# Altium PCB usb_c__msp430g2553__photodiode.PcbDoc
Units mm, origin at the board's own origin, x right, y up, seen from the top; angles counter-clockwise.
Board outline 56 x 30 mm, 2 copper layers (Top, Bottom), stack 0 mm thick; 27 components, 18 nets, 126 pads, 36 vias.
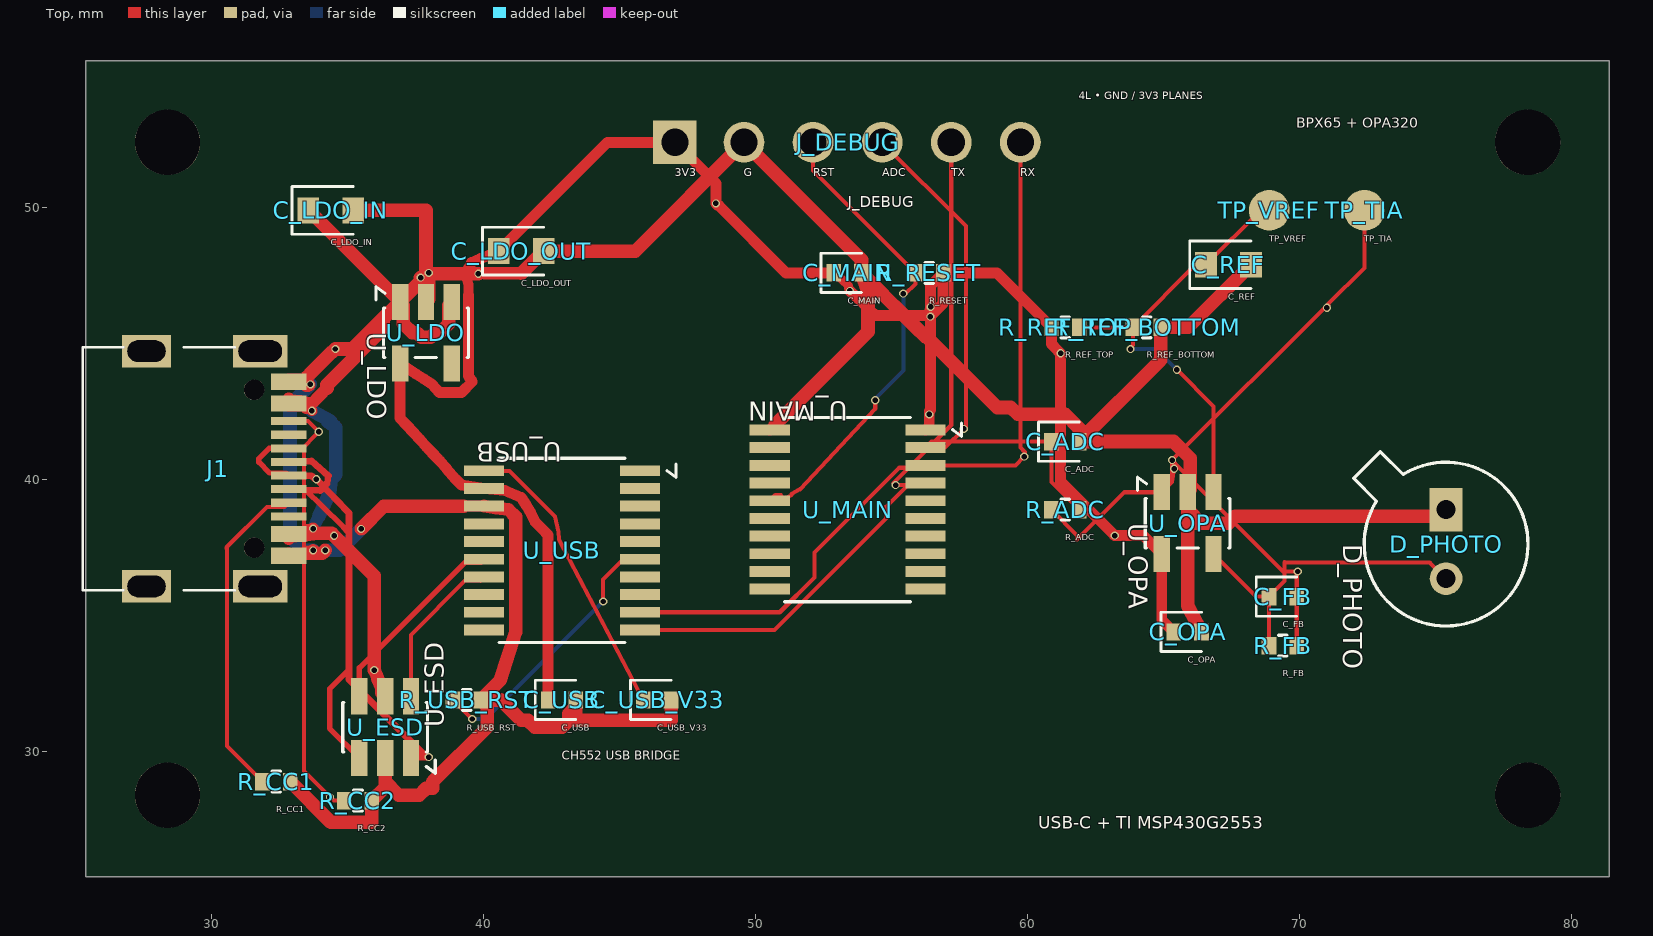
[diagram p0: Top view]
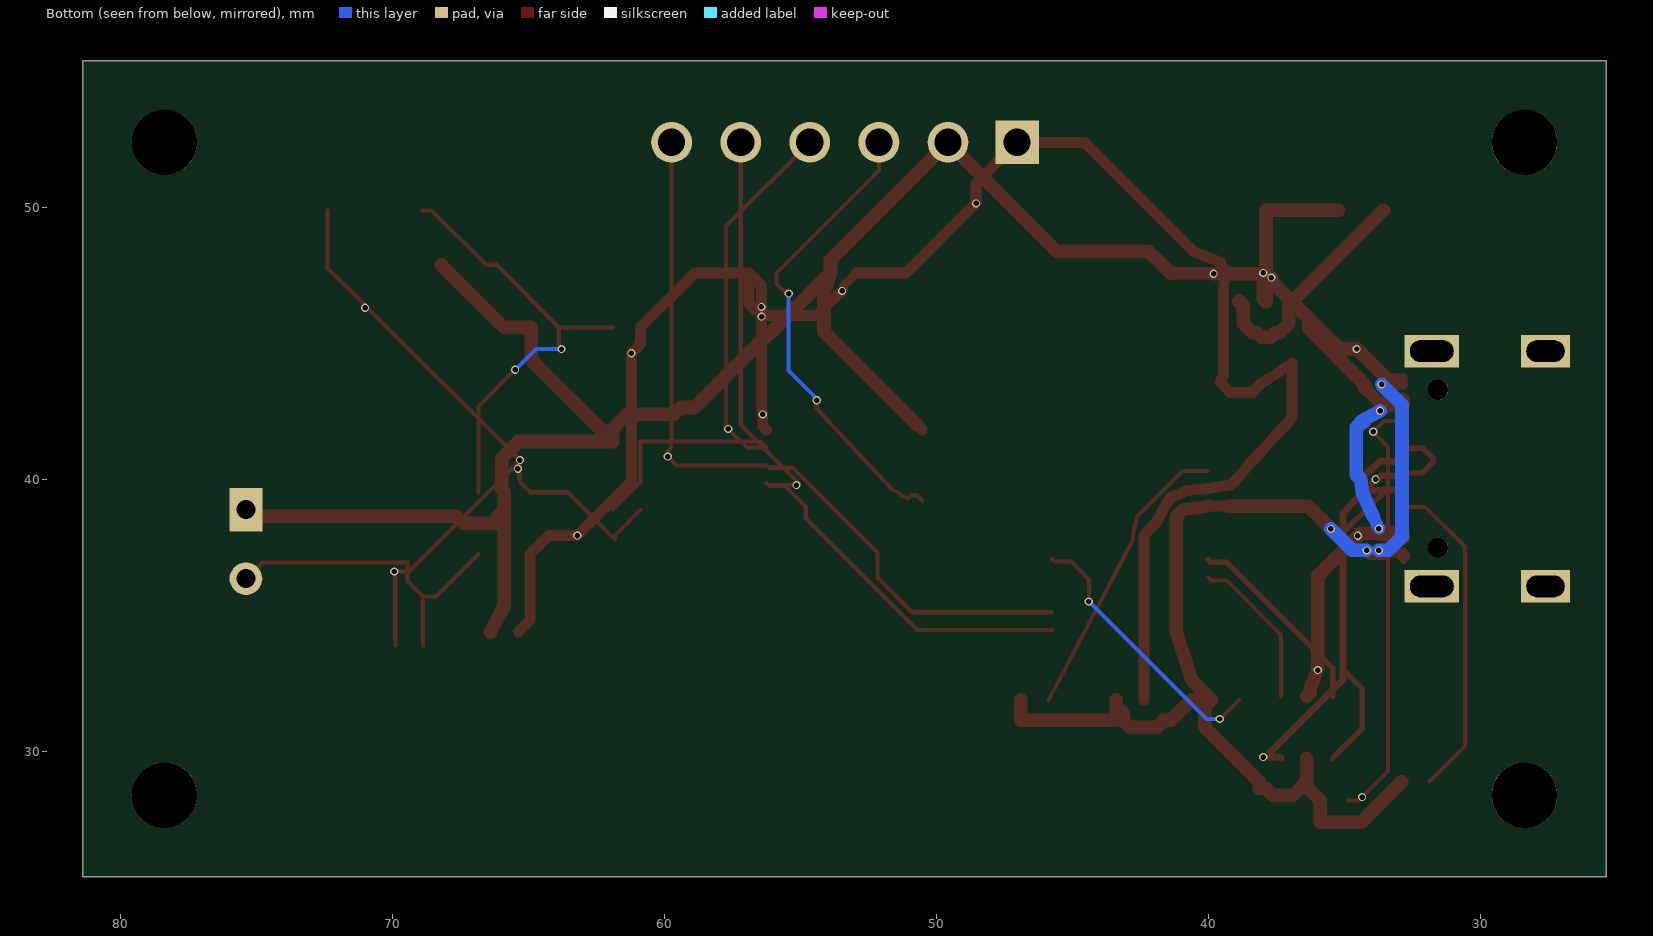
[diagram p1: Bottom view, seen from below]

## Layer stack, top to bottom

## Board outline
25.4,55.4 81.4,55.4 81.4,25.4 25.4,25.4

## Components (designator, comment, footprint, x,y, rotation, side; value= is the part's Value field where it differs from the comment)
C_ADC "" TSCIRCUIT-1.5600x0.6400mm 61.4,41.4 r0 top
C_FB "" TSCIRCUIT-1.5600x0.6400mm 69.4,35.7 r0 top
C_LDO_IN "" TSCIRCUIT-2.4500x0.9500mm 34.4,49.9 r0 top
C_LDO_OUT "" TSCIRCUIT-2.4500x0.9500mm 41.4,48.4 r0 top
C_MAIN "" TSCIRCUIT-1.5600x0.6400mm 53.4,47.6 r0 top
C_OPA "" TSCIRCUIT-1.5600x0.6400mm 65.9,34.4 r0 top
C_REF "" TSCIRCUIT-2.4500x0.9500mm 67.4,47.9 r0 top
C_USB "" TSCIRCUIT-1.5600x0.6400mm 42.9,31.9 r0 top
C_USB_V33 "" TSCIRCUIT-1.5600x0.6400mm 46.4,31.9 r0 top
D_PHOTO "" TSCIRCUIT-1.2000x3.9400mm 75.4,37.73 r270 top
J1 "" TSCIRCUIT-6.7732x9.8502mm 30.113,40.4 r90 top
J_DEBUG "" TSCIRCUIT-14.2000x1.5000mm 53.4,52.4 r0 top
R_ADC "" TSCIRCUIT-1.5600x0.6400mm 61.4,38.9 r0 top
R_CC1 "" TSCIRCUIT-1.5600x0.6400mm 32.4,28.9 r0 top
R_CC2 "" TSCIRCUIT-1.5600x0.6400mm 35.4,28.2 r0 top
R_FB "" TSCIRCUIT-1.5600x0.6400mm 69.4,33.9 r0 top
R_REF_BOTTOM "" TSCIRCUIT-1.5600x0.6400mm 64.4,45.6 r0 top
R_REF_TOP "" TSCIRCUIT-1.5600x0.6400mm 61.4,45.6 r0 top
R_RESET "" TSCIRCUIT-1.5600x0.6400mm 56.4,47.6 r0 top
R_USB_RST "" TSCIRCUIT-1.5600x0.6400mm 39.4,31.9 r0 top
TP_TIA "" TSCIRCUIT-1.5000x1.5000mm 72.4,49.9 r0 top
TP_VREF "" TSCIRCUIT-1.5000x1.5000mm 68.9,49.9 r0 top
U_ESD "" TSCIRCUIT-2.5000x3.6000mm#1 36.4,30.9 r90 top
U_LDO "" TSCIRCUIT-2.5000x3.6000mm#2 37.9,45.4 r270 top
U_MAIN "" TSCIRCUIT-7.2000x6.2500mm 53.4,38.9 r180 top
U_OPA "" TSCIRCUIT-2.5000x3.6000mm#2 65.9,38.4 r270 top
U_USB "" TSCIRCUIT-7.2000x6.2500mm 42.9,37.4 r180 top

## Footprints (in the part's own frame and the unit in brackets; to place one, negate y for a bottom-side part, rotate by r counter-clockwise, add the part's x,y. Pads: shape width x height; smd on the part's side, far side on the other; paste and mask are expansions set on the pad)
TSCIRCUIT-1.2000x3.9400mm [mm]
  rect 1.6x1.2 hole 0.7: 1(-1.17,0)
  round 1.2 hole 0.7: 2(1.37,0)
  silkscreen extent -3.3,-3.4 3.11,3.01
TSCIRCUIT-1.5000x1.5000mm [mm]
  round 1.5 smd: 1(0,0)
TSCIRCUIT-1.5600x0.6400mm [mm]
  rect 0.54x0.64 smd: 1(-0.51,0) 2(0.51,0)
  silkscreen extent -0.98,-0.72 0.51,0.72
TSCIRCUIT-2.4500x0.9500mm [mm]
  rect 0.8x0.95 smd: 1(-0.825,0) 2(0.825,0)
  silkscreen extent -1.43,-0.87 0.82,0.87
TSCIRCUIT-2.5000x3.6000mm#1 [mm]
  rect 1.325x0.6 smd: 1(-1.137,-0.95) 2(-1.137,0) 3(-1.137,0.95) 4(1.138,0.95) 5(1.138,0) 6(1.138,-0.95)
  silkscreen extent -1.69,-1.84 0.91,1.56
TSCIRCUIT-2.5000x3.6000mm#2 [mm]
  rect 1.325x0.6 smd: 1(-1.137,-0.95) 2(-1.137,0) 3(-1.137,0.95) 4(1.138,0.95) 5(1.138,-0.95)
  silkscreen extent -1.69,-1.84 0.91,1.56
TSCIRCUIT-6.7732x9.8502mm [mm]
  rect 1.2x2 hole 0.8 slot 1.6 at 90 deg: 1(-4.325,-1.693) 1(4.325,-1.693)
  rect 1.2x1.8 hole 0.8 slot 1.4 at 90 deg: 1(-4.325,2.487) 1(4.325,2.487)
  rect 0.3x1.3 smd: 1(-3.35,-2.737) 2(-3.05,-2.737) 3(-2.55,-2.737) 4(-2.25,-2.737) 5(-1.75,-2.737) 6(-1.25,-2.737) 7(-0.75,-2.737) 8(-0.25,-2.737) 9(0.25,-2.737) 10(0.75,-2.737) 11(1.25,-2.737) 12(1.75,-2.737) 13(2.55,-2.737) 14(2.25,-2.737) 15(3.35,-2.737) 16(3.05,-2.737)
  round 0.75 hole 0.75 unplated: NPTH-1(-2.9,-1.468) NPTH-2(2.9,-1.468)
  silkscreen extent -4.47,-0.75 4.47,4.83
TSCIRCUIT-7.2000x6.2500mm [mm]
  rect 1.475x0.4 smd: 1(-2.863,-2.925) 2(-2.863,-2.275) 3(-2.863,-1.625) 4(-2.863,-0.975) 5(-2.863,-0.325) 6(-2.863,0.325) 7(-2.863,0.975) 8(-2.863,1.625) 9(-2.863,2.275) 10(-2.863,2.925) 11(2.862,2.925) 12(2.862,2.275) 13(2.862,1.625) 14(2.862,0.975) 15(2.862,0.325) 16(2.862,-0.325) 17(2.862,-0.975) 18(2.862,-1.625) 19(2.862,-2.275) 20(2.862,-2.925)
  silkscreen extent -4.19,-3.38 2.31,3.39
TSCIRCUIT-14.2000x1.5000mm [mm]
  rect 1.6x1.6 hole 1: 1(-6.35,0)
  round 1.5 hole 1: 2(-3.81,0) 3(-1.27,0) 4(1.27,0) 5(3.81,0) 6(6.35,0)

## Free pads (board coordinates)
  round 2.4 hole 2.4 unplated: NPTH-3(28.4,28.4) NPTH-4(78.4,52.4) NPTH-5(78.4,28.4) NPTH-6(28.4,52.4)

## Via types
v1: diameter 0.3, hole 0.2, Top to Bottom, 36 vias

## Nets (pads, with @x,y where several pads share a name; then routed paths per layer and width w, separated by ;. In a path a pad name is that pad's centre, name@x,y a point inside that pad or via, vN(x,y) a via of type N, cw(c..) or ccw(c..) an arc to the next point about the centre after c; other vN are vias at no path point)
ADC_IN: C_ADC.1 J_DEBUG.4 R_ADC.2 U_MAIN.2 | length 21.2
  Top w0.15: J_DEBUG.4 57.745,49.325 57.745,41.972 57.745,41.938 v1(57.671,41.864) 56.982,41.175 U_MAIN.2 56.487,41.4 C_ADC.1 60.89,39.92 R_ADC.2
GND: C_ADC.2 C_LDO_IN.2 C_LDO_OUT.2 C_MAIN.2 C_OPA.2 C_REF.2 C_USB.2 C_USB_V33.2 D_PHOTO.1 J1.1@32.849,37.05 J1.2 J1.15 J1.16 J_DEBUG.2 R_CC1.2 R_CC2.2 R_REF_BOTTOM.2 R_USB_RST.2 U_ESD.2 U_LDO.2 U_MAIN.20 U_OPA.2 U_USB.18 | length 133.5
  Top w0.288: J1.16@32.849,43.6 J1.16 32.946,43.468 J1.16@33.037,43.45
  Top w0.3: J1.1@32.849,37.05 32.849,37.2 J1.2 ; J1.16@32.849,43.6 J1.15 32.974,43.75 33.099,43.75 33.224,43.75 33.349,43.75 33.474,43.75 J1.15@33.497,43.75 ; J1.16@33.13,43.45 33.224,43.45 33.318,43.45 33.412,43.45 33.499,43.45 33.505,43.45 ; 33.499,37.296 33.125,37.296 33,37.252 J1.2 ; 33.499,37.349 33.334,37.349 32.903,37.325 J1.2
  Top w0.301: J1.16@33.037,43.45 J1.16@33.13,43.45
  Top w0.325: v1(39.828,47.571) 39.845,47.588 40.062,47.588
  Top w0.35: v1@33.596,43.477 v1(33.65,43.5)
  Top w0.4: 39.288,39.025 39.3,39.025 39.412,39.025 39.538,39.025 39.662,39.025 39.787,39.025 39.913,39.025 U_USB.18 ; U_MAIN.20 50.737,42.025
  Top w0.45: 40.062,47.588 40.512,47.588 40.962,47.588 41.413,47.588
  Top w0.475: 33.499,37.349 33.699,37.349 v1(33.75,37.4) ; 33.505,43.45 33.561,43.45 33.588,43.477 v1@33.596,43.477 ; U_USB.18 40.484,38.963 40.931,38.9 41.119,38.713
  Top w0.5: R_CC1.2 34.41,27.4 35.91,27.4 R_CC2.2 36.4,28.69 U_ESD.2 36.4,28.9 36.9,28.4 37.65,28.4 37.9,28.65 38.15,28.65 38.15,28.9 40.15,30.9 40.15,31.65 39.91,31.89 R_USB_RST.2 ; J1.15@33.497,43.75 33.499,43.751 33.569,43.822 33.658,43.91 33.746,43.999 34.453,44.706 34.475,44.706 v1(34.571,44.802) 35.202,44.802 v1(38,47.6) U_LDO.2@38,46.637 ; 33.499,37.296 34.093,37.296 v1(34.194,37.397) ; C_LDO_IN.2 37.9,49.9 U_LDO.2 ; v1(35.513,38.189) 36.349,39.025 39.037,39.025 39.162,39.025 39.288,39.025 ; v1(39.828,47.571) 39.399,47.571 38.969,47.571 38.54,47.571 38.11,47.571 38.088,47.593 38.007,47.593 v1(37.7,47.425) 38,47.119 U_LDO.2@38,46.637 ; 41.119,38.713 41.2,38.631 41.2,34.4 40.616,32.606 40.263,32.253 R_USB_RST.2 ; 41.413,47.588 41.683,47.858 41.954,48.129 C_LDO_OUT.2 45.59,48.4 J_DEBUG.2 53.91,48.08 C_MAIN.2 ; C_USB_V33.2 46.91,31.15 43.41,31.15 C_USB.2 43.4,31.9 43.4,31.65 43.15,31.4 43.15,31.15 42.9,30.9 41.9,30.9 41.65,31.15 41.4,31.15 40.65,31.9 R_USB_RST.2 ; 50.738,42.025 54.15,45.438 54.15,46.9 C_MAIN.2 ; C_OPA.2 65.9,35.373 65.9,35.836 65.9,36.298 65.9,36.761 65.9,37.224 65.9,37.687 65.9,38.149 65.9,38.612 65.9,39.075 U_OPA.2 ; C_REF.2 65.925,45.6 R_REF_BOTTOM.2 64.91,44.4 C_ADC.2 ; D_PHOTO.1 75.152,38.652 74.654,38.652 74.155,38.652 73.656,38.652 73.158,38.652 72.902,38.652 72.9,38.65 67.65,38.65 67.4,38.4 66.15,38.4 66.15,38.65 65.9,38.9 U_OPA.2 ; U_LDO.2 U_LDO.2@38,46.637 ; U_LDO.2 U_LDO.2@38,46.637 ; C_MAIN.2 54.244,47.266 54.579,46.931 54.913,46.597 55.248,46.262 55.582,45.928 55.917,45.593 56.251,45.259 56.291,45.259 58.9,42.65 59.4,42.65 59.65,42.4 61.4,42.4 61.91,41.89 C_ADC.2 ; C_ADC.2 65.384,41.4 65.999,40.785 65.999,39.637 U_OPA.2
  Bottom w0.5: v1(33.65,43.5) 32.9,42.75 32.9,37.9 33.4,37.4 v1(33.75,37.4) ; v1(34.194,37.397) 34.721,37.397 v1(35.513,38.189)
MAIN_RESET: J_DEBUG.3 R_RESET.1 U_MAIN.16 | length 17.4
  Top w0.15: U_MAIN.16 50.738,39.426 50.951,39.426 51.061,39.304 51.343,39.428 51.343,39.478 51.644,39.645 54.415,42.606 v1(54.415,42.921) ; J_DEBUG.3 52.13,51.36 R_RESET.1 55.89,47.192 55.517,46.819 55.468,46.819 v1(55.448,46.839)
  Bottom w0.15: v1(54.415,42.921) 54.448,42.954 54.448,43.005 55.448,44.005 v1(55.448,46.839)
PD_SUM: C_FB.1 D_PHOTO.2 R_FB.1 U_OPA.4 | length 12.2
  Top w0.15: U_OPA.4 68.412,35.7 C_FB.1 ; R_FB.1 C_FB.1 ; D_PHOTO.2 74.799,36.961 69.465,36.962 69.465,36.275 C_FB.1
TIA_OUT: C_FB.2 R_ADC.1 R_FB.2 TP_TIA.1 U_OPA.1 | length 29
  Top w0.15: R_ADC.1 61.839,37.951 61.839,37.801 63.575,39.538 U_OPA.1 ; R_FB.2 C_FB.2 69.91,36.45 69.91,36.584 v1(69.95,36.622) 69.406,36.624 65.43,40.599 65.43,40.616 v1(65.4,40.4) 65.33,39.917 ; TP_TIA.1 72.4,47.784 71.068,46.452 71.068,46.365 v1(71.021,46.318) 70.932,46.318 65.443,40.829 v1(65.33,40.716) 65.33,39.917 ; U_OPA.1 65.33,39.917 ; U_OPA.1 65.33,39.917
UART_MAIN_RX: J_DEBUG.6 U_MAIN.3 U_USB.9 | length 28.7
  Top w0.15: U_USB.9 50.905,35.125 52.185,36.404 52.185,37.323 55.299,40.438 56.175,40.438 U_MAIN.3 59.568,40.525 v1(59.891,40.848) 59.912,40.869 59.912,41.023 59.75,41.185 J_DEBUG.6
UART_MAIN_TX: J_DEBUG.5 U_MAIN.4 U_USB.10 | length 27.6
  Top w0.15: U_USB.10 50.713,34.475 54.821,38.583 54.821,39.005 55.584,39.767 56.154,39.767 U_MAIN.4 56.188,39.8 v1(55.163,39.8) 55.081,39.882 57.21,42.012 J_DEBUG.5
USB_BRIDGE_RESET: R_USB_RST.1 U_USB.6 | length 10.1
  Top w0.15: R_USB_RST.1 38.9,31.9 39.594,31.206 v1(39.6,31.2) ; v1(44.415,35.52) 44.415,36.331 45.077,36.993 45.68,36.993 U_USB.6
  Bottom w0.15: v1(39.6,31.2) 40.095,31.2 44.34,35.445 v1(44.415,35.52)
USB_BRIDGE_V33: C_USB_V33.1 U_USB.20 | length 10.8
  Top w0.15: U_USB.20 40.968,40.325 42.647,38.649 42.769,38.079 42.783,37.808 C_USB_V33.1
USB_CC1: J1.6 R_CC1.1 | length 12.1
  Top w0.15: R_CC1.1 30.578,30.212 30.578,37.356 30.576,37.515 32.057,38.994 32.692,38.993 J1.6
USB_CC2: J1.12 R_CC2.1 | length 15.9
  Top w0.15: J1.12 33.568,42.15 v1(33.96,41.758) 33.802,41.6 33.409,41.207 33.409,41.014 33.409,29.291 v1(34.37,28.33) 34.407,28.293 34.429,28.293 34.522,28.2 R_CC2.1
USB_DM_MCU: U_ESD.4 U_USB.15 | length 7.3
  Top w0.2: U_ESD.4 35.45,33.078 39.334,36.963 39.925,36.963 U_USB.15
USB_DM_PORT: J1.7 J1.9 U_ESD.3 | length 15.4
  Top w0.2: J1.7 33.437,39.65 34.814,38.31 35.083,38.005 35.083,33.035 34.355,32.307 34.355,30.857 U_ESD.3
  Top w0.25: J1.7 34.012,39.601 34.271,39.876 34.311,40.142 33.692,40.689 J1.9
USB_DP_MCU: U_ESD.6 U_USB.14 | length 5.8
  Top w0.15: U_ESD.6 37.35,34.285 39.342,36.287 39.894,36.282 U_USB.14
USB_DP_PORT: J1.8 J1.10 U_ESD.1 | length 16.4
  Top w0.2: J1.8 32.755,40.244 32.156,40.244 31.755,40.645 31.755,40.774 32.131,41.15 J1.10
  Top w0.25: J1.8 33.686,40.142 33.798,40.035 v1(33.87,40.015) 35.066,38.778 35.066,32.656 37.894,29.828 37.972,29.828 v1(38,29.8) 37.388,29.8 U_ESD.1
VBUS5: C_LDO_IN.1 J1.3 J1.4 J1.13 J1.14 U_ESD.5 U_LDO.1 U_LDO.3 | length 30.6
  Top w0.3: J1.3 J1.3@33.1,37.9 ; J1.3@32.849,38 J1.4 33.499,38.15 ; J1.14@32.849,42.8 J1.14 33.499,42.65
  Top w0.4: 33.595,42.642 v1(33.706,42.531)
  Top w0.425: J1.3@33.1,37.9 33.5,37.967
  Top w0.437: J1.13@33.281,42.878 33.713,42.806 33.986,43.08 34.259,43.353 ; v1@33.699,38.15 v1(33.749,38.2)
  Top w0.45: J1.13 J1.13@33.281,42.878 ; 33.499,38.15 v1@33.699,38.15
  Top w0.475: 33.499,42.65 33.587,42.65 33.595,42.642 ; v1(36,33) U_ESD.5@36.133,32.679
  Top w0.5: J1.3 J1.3@32.849,38 ; J1.13@32.849,42.8 J1.13@32.849,42.95 ; 33.5,37.967 33.9,38.033 34.426,38.033 v1(34.522,37.937) 36,36.459 v1(36,33) ; C_LDO_IN.1 33.587,49.9 U_LDO.1 ; 34.259,43.353 34.259,43.481 36.324,45.545 36.324,45.912 U_LDO.1 ; U_ESD.5@36.133,32.679 36.267,32.358 36.267,32.171 U_ESD.5 ; U_LDO.3 38.879,46.567 38.9,46.567 38.733,46.4 38.733,45.733 38.4,45.4 38.233,45.4 38.067,45.233 37.733,45.233 37.567,45.4 37.4,45.4 37.067,45.733 37.067,46.4 36.95,46.517 U_LDO.1
  Bottom w0.45: v1(33.749,38.2) 33.955,38.642
  Bottom w0.5: v1(33.706,42.531) 34.4,42.15 34.294,42.131 34.588,41.931 34.588,40.181 34.412,40.006 34.369,39.525 34.162,39.083 33.955,38.642
VCC_3V3: C_LDO_OUT.1 C_MAIN.1 C_OPA.1 C_USB.1 J_DEBUG.1 R_REF_TOP.1 R_RESET.2 U_LDO.5 U_MAIN.1 U_OPA.5 U_USB.19 | length 71
  Top w0.325: C_MAIN.1@52.952,47.6 53.191,47.361 53.431,47.121 53.431,47.041 v1(53.486,46.94)
  Top w0.35: 39.4,47.4 39.342,47.633 39.458,47.808 39.575,47.983
  Top w0.375: 39.4,47.4 39.458,47.167 39.458,46.793
  Top w0.4: 39.458,46.793 39.458,46.42 39.458,46.047 39.458,45.673 39.458,45.3 39.458,44.927 39.458,44.553 39.458,44.18 39.458,43.807 39.6,43.6 39.2,43.2 38.4,43.2 38.117,43.506 37.825,43.695 37.533,43.884 37.242,44.073 U_LDO.5 36.95,43.929 36.95,43.595 36.95,43.262 36.95,42.928 36.95,42.594 36.95,42.261 37.193,41.997 37.436,41.733 37.679,41.47 37.923,41.206 38.166,40.942 38.409,40.678 38.652,40.414 39,40 39.2,39.8 U_USB.19 40.8,39.6 41.4,39.35 41.585,39.058 41.768,38.757 41.9,38.455 42.141,38.213 42.382,37.97 42.383,37.591 42.383,37.211 42.384,36.832 42.384,36.452 42.385,36.073 42.385,35.694 42.386,35.314 42.386,34.935 42.387,34.556 42.387,34.176 42.388,33.797 42.388,33.417 42.389,33.038 42.389,32.659 42.39,32.279 C_USB.1 ; 39.575,47.983 39.908,48.122 40.242,48.261 C_LDO_OUT.1 44.575,52.4 J_DEBUG.1 48.557,50.893 v1(48.557,50.154) 48.637,50.074 48.665,50.074 51.139,47.6 C_MAIN.1 C_MAIN.1@52.952,47.6 ; v1(53.486,46.94) 53.724,46.714 53.962,46.487 54.199,46.261 54.437,46.035 54.831,46.035 55.224,46.035 55.618,46.035 56.011,46.035 56.405,46.035 v1(56.45,46.35) 56.445,46.375 56.445,46.755 56.445,47.135 56.677,47.367 R_RESET.2 ; U_MAIN.1 56.4,41.963 v1(56.4,42.4) 56.402,42.402 56.402,42.514 56.445,42.556 v1(56.445,45.995) 56.469,46.019 56.469,46.033 56.91,46.473 R_RESET.2 ; C_OPA.1 64.95,34.84 U_OPA.5 64.267,37.945 v1(63.22,37.945) 63.199,37.966 61.228,39.937 v1(61.228,44.647) 61.14,44.735 60.89,44.985 R_REF_TOP.1 58.89,47.6 R_RESET.2
VREF_0V5: C_REF.1 R_REF_BOTTOM.1 R_REF_TOP.2 TP_VREF.1 U_OPA.3 | length 16.7
  Top w0.15: R_REF_TOP.2 R_REF_BOTTOM.1 ; v1(63.8,44.8) 63.818,44.818 63.818,44.88 63.89,44.952 R_REF_BOTTOM.1 ; v1(65.503,44.042) 66.85,42.695 U_OPA.3 ; TP_VREF.1 68.575,49.9 C_REF.1 66.19,47.9 R_REF_BOTTOM.1
  Bottom w0.15: v1(63.8,44.8) 64.745,44.8 65.489,44.056 v1(65.503,44.042)
pads on no net: J1.1@27.626,36.075 J1.1@27.626,44.725 J1.1@31.806,36.075 J1.1@31.806,44.725 J1.5 J1.11 J1.NPTH-1 J1.NPTH-2 U_LDO.4 U_MAIN.5 U_MAIN.6 U_MAIN.7 U_MAIN.8 U_MAIN.9 U_MAIN.10 U_MAIN.11 U_MAIN.12 U_MAIN.13 U_MAIN.14 U_MAIN.15 U_MAIN.17 U_MAIN.18 U_MAIN.19 U_USB.1 U_USB.2 U_USB.3 U_USB.4 U_USB.5 U_USB.7 U_USB.8 U_USB.11 U_USB.12 U_USB.13 U_USB.16 U_USB.17

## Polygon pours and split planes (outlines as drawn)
GND on Mid1 (solid): 81.1,55.1 25.7,55.1 25.7,25.7 81.1,25.7
VCC_3V3 on Mid2 (solid): 81.1,55.1 25.7,55.1 25.7,25.7 81.1,25.7

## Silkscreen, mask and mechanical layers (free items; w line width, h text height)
Top Overlay:
  text "4L • GND / 3V3 PLANES" at 61.9,53.9 h0.48
  text "BPX65 + OPA320" at 69.9,52.8 h0.65
  text "CH552 USB BRIDGE" at 42.9,29.6 h0.55
  text "USB-C + TI MSP430G2553" at 60.4,27 h0.78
